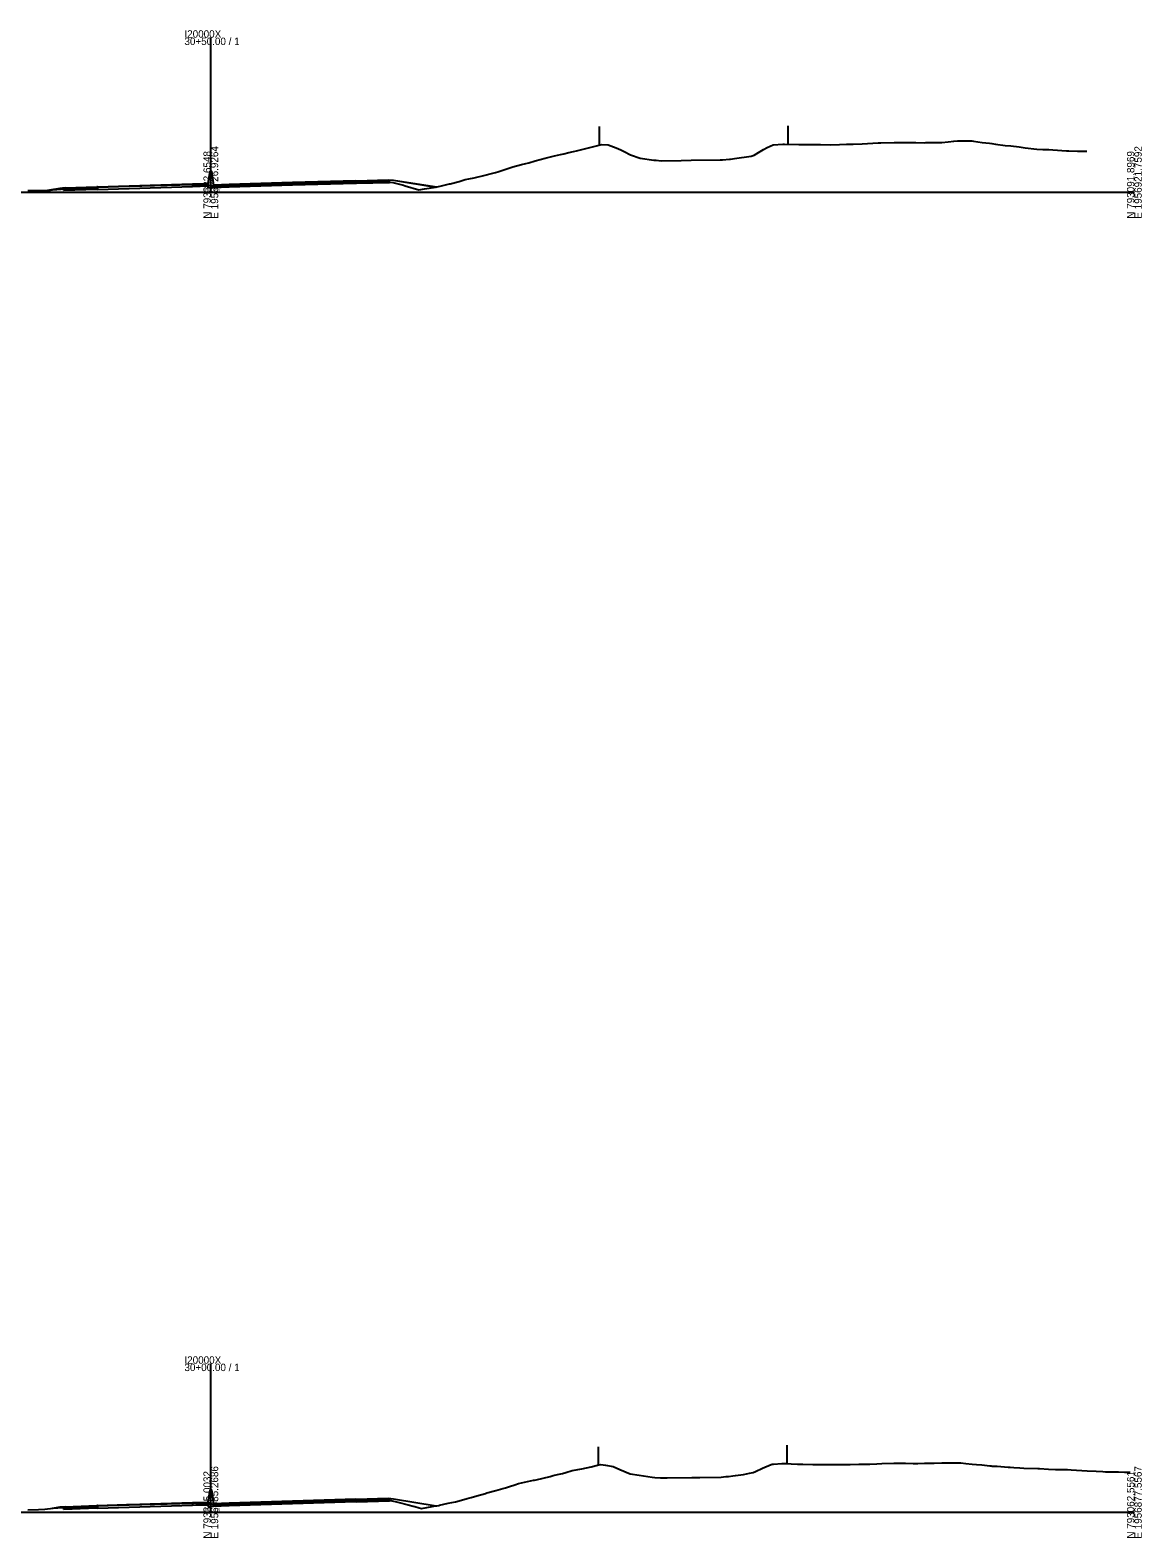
# Model space of a CAD drawing. Extents: x -4026 to 9638, y -10 to 19609.
# Drawn here: x -2718 to -2297, y -10 to 561 of the extents above; entities that cross this region are included whole.
import ezdxf

# ---------------------------------------------------------------- set-up
doc = ezdxf.new("R2010")
doc.units = 0
for name, color, linetype in [('RD_EX_Fence_Other', 7, 'Continuous'), ('RD_GPK_XS_Cell', 7, 'Continuous'), ('RD_XS_Base', 7, 'Continuous'), ('RD_XS_ExGround', 7, 'Continuous'), ('RD_XS_Greenside', 7, 'Continuous'), ('RD_XS_MedBWall', 7, 'Continuous'), ('RD_XS_Pave', 7, 'Continuous'), ('RD_XS_PaveOvlay', 7, 'Continuous'), ('RD_XS_TieSlope', 7, 'Continuous'), ('RD_XS_TX_Elev_EX', 7, 'Continuous')]:
    doc.layers.add(name, color=color, linetype=linetype)

msp = doc.modelspace()

# ---------------------------------------------------------------- linework, layer by layer
at = {"layer": 'RD_EX_Fence_Other'}
for p, q in [((-2502.77, 524.9), (-2502.77, 517.9)), ((-2431.34, 525.15), (-2431.34, 518.15)), ((-2503.21, 24.84), (-2503.21, 17.84)), ((-2431.68, 25.41), (-2431.68, 18.41))]:
    msp.add_line(p, q, dxfattribs=at)
at = {"layer": 'RD_GPK_XS_Cell'}
for p, q in [((-2650, 500), (-2650, 558.57)), ((-3000, 500), (-2650, 500)), ((-2650, 500), (-2300, 500)), ((-2650, 0), (-2650, 56.27)), ((-3000, 0), (-2650, 0)), ((-2650, 0), (-2300, 0))]:
    msp.add_line(p, q, dxfattribs=at)
at = {"layer": 'RD_XS_Base'}
for points in [[(-2657, 502.86), (-2681, 502.14), (-2693, 501.78)], [(-2651, 503.05), (-2657, 502.86)], [(-2657, 502.86), (-2657, 502.19)], [(-2651, 502.38), (-2651, 503.05)], [(-2649, 502.37), (-2643, 502.61)], [(-2643, 502.61), (-2619, 503.33), (-2595, 504.05)], [(-2595, 503.38), (-2619, 502.66), (-2643, 501.94)], [(-2643, 501.94), (-2643, 502.61)], [(-2595, 504.05), (-2594.75, 504.06)], [(-2595, 503.38), (-2595, 504.05)], [(-2594.75, 503.39), (-2595, 503.38)], [(-2582.25, 504.43), (-2582.75, 504.42), (-2594.75, 504.06)], [(-2594.75, 504.06), (-2594.75, 503.39)], [(-2594.75, 503.39), (-2582.25, 503.76)], [(-2582.25, 503.76), (-2582.25, 504.43)], [(-2705.75, 501.28), (-2705.25, 501.3), (-2693.25, 501.77)], [(-2705.75, 500.61), (-2705.75, 501.28)], [(-2693.25, 501.1), (-2705.75, 500.61)], [(-2693.25, 501.77), (-2693, 501.78)], [(-2693.25, 501.1), (-2693.25, 501.77)], [(-2693, 501.11), (-2693.25, 501.1)], [(-2693, 501.11), (-2681, 501.47), (-2657, 502.19)], [(-2693, 501.78), (-2693, 501.11)], [(-2657, 502.19), (-2651, 502.38)], [(-2649, 501.7), (-2649, 502.37)], [(-2643, 501.94), (-2649, 501.7)], [(-2705.75, 1.76), (-2705.25, 1.78), (-2693.25, 2.25)], [(-2705.75, 1.09), (-2705.75, 1.76)], [(-2693.25, 1.58), (-2705.75, 1.09)], [(-2693.25, 2.25), (-2693, 2.26)], [(-2693.25, 1.58), (-2693.25, 2.25)], [(-2693, 1.59), (-2693.25, 1.58)], [(-2657, 3.35), (-2681, 2.63), (-2693, 2.26)], [(-2693, 1.59), (-2681, 1.96), (-2657, 2.68)], [(-2693, 2.26), (-2693, 1.59)], [(-2651, 3.53), (-2657, 3.35)], [(-2657, 3.35), (-2657, 2.68)], [(-2657, 2.68), (-2651, 2.86)], [(-2651, 2.86), (-2651, 3.53)], [(-2649, 2.9), (-2643, 3.14)], [(-2649, 2.23), (-2649, 2.9)], [(-2643, 2.47), (-2649, 2.23)], [(-2643, 3.14), (-2619, 3.87), (-2595, 4.58)], [(-2595, 3.91), (-2619, 3.2), (-2643, 2.47)], [(-2643, 2.47), (-2643, 3.14)], [(-2595, 4.58), (-2594.75, 4.59)], [(-2595, 3.91), (-2595, 4.58)], [(-2594.75, 3.92), (-2595, 3.91)], [(-2582.25, 4.97), (-2582.75, 4.96), (-2594.75, 4.59)], [(-2594.75, 4.59), (-2594.75, 3.92)], [(-2594.75, 3.92), (-2582.25, 4.3)], [(-2582.25, 4.3), (-2582.25, 4.97)]]:
    msp.add_lwpolyline(points, dxfattribs=at)
at = {"layer": 'RD_XS_ExGround'}
for points in [[(-2719.34, 500.67), (-2717.96, 500.65), (-2717.22, 500.65), (-2714.42, 500.66), (-2711.93, 500.78), (-2710.81, 500.83), (-2710.06, 500.9), (-2703.43, 501.42), (-2702.25, 501.52), (-2693.3, 501.94), (-2681.86, 502.29), (-2674.2, 502.53), (-2670.1, 502.65), (-2662.32, 502.85), (-2658.4, 502.95), (-2655.83, 502.9), (-2652.91, 502.85), (-2651.82, 502.77), (-2650, 502.62), (-2649.02, 502.55), (-2644.92, 502.82), (-2643.82, 502.89), (-2643.25, 502.91), (-2641.06, 503), (-2640.26, 503.03), (-2639.84, 503.04), (-2637.84, 503.11), (-2632.31, 503.24), (-2631.6, 503.26), (-2620.57, 503.59), (-2619.97, 503.61), (-2618.47, 503.64), (-2609, 503.86), (-2600.66, 504.09), (-2600.02, 504.11), (-2599.06, 504.11), (-2590.13, 504.11), (-2588.31, 504.04), (-2586.89, 503.99), (-2586.24, 503.97), (-2583.67, 503.86), (-2581.07, 503.64), (-2577.47, 502.82), (-2576.95, 502.67), (-2576.39, 502.5), (-2571.21, 500.98), (-2568.98, 501.32), (-2568.19, 501.43), (-2565.61, 501.86), (-2563.05, 502.37), (-2559.59, 503.16), (-2559.24, 503.25), (-2555.85, 504.12), (-2553.57, 504.8), (-2552.24, 505.15), (-2550.26, 505.53), (-2548.64, 505.84), (-2547.56, 506.09), (-2542.07, 507.53), (-2541.27, 507.75), (-2535.52, 509.64), (-2532.29, 510.5), (-2530.62, 510.91), (-2529.5, 511.21), (-2527.02, 511.92), (-2523.31, 512.94), (-2519.81, 513.79), (-2517.46, 514.29), (-2516.2, 514.6), (-2514.33, 515.07), (-2512.6, 515.5), (-2511.44, 515.72), (-2505.35, 517.25), (-2501.79, 518.15), (-2499.4, 517.92), (-2496.36, 516.85), (-2494.58, 516.05), (-2493.39, 515.48), (-2490.98, 514.23), (-2487.32, 512.93), (-2482.11, 512.17), (-2481.17, 512.11), (-2479.31, 511.97), (-2471.69, 512.07), (-2467.99, 512.11), (-2456.93, 512.29), (-2456.14, 512.3), (-2453.39, 512.52), (-2453.05, 512.56), (-2451.59, 512.74), (-2445.24, 513.69), (-2444.13, 514.06), (-2442.47, 515.06), (-2440.52, 516.16), (-2439.22, 516.95), (-2436.92, 517.95), (-2433.2, 518.17), (-2432.61, 518.16), (-2427.18, 518.1), (-2424.51, 518.1), (-2421.16, 518.05), (-2418.9, 518.12), (-2415.14, 518.03), (-2411.69, 518.12), (-2409.12, 518.23), (-2408.09, 518.26), (-2406.54, 518.28), (-2403.1, 518.37), (-2397.09, 518.76), (-2396.12, 518.78), (-2391.07, 518.88), (-2388.58, 518.88), (-2386.47, 518.82), (-2385.05, 518.84), (-2382.86, 518.85), (-2379.6, 518.77), (-2379.03, 518.79), (-2377.88, 518.8), (-2373.01, 518.91), (-2370.62, 519.08), (-2368.45, 519.39), (-2366.99, 519.49), (-2364.84, 519.52), (-2361.63, 519.46), (-2360.97, 519.4), (-2357.63, 518.88), (-2354.95, 518.6), (-2354.03, 518.47), (-2352.65, 518.27), (-2348.94, 517.71), (-2346.82, 517.54), (-2343.67, 517.16), (-2342.92, 517.07), (-2341.39, 516.87), (-2336.9, 516.28), (-2334.69, 516.17), (-2332.41, 516.14), (-2330.88, 516.06), (-2325.71, 515.69), (-2325.2, 515.65), (-2324.86, 515.64), (-2321.6, 515.52), (-2318.84, 515.57), (-2317.99, 515.57)], [(-2719.32, 0.98), (-2715.25, 1), (-2712.89, 1.2), (-2709.74, 1.52), (-2708.03, 1.67), (-2705.8, 1.84), (-2705.27, 1.88), (-2704.08, 1.94), (-2701.83, 2.11), (-2698.98, 2.25), (-2693.26, 2.52), (-2685.55, 2.78), (-2681.95, 2.9), (-2679.16, 2.98), (-2670.34, 3.2), (-2665.13, 3.34), (-2658.54, 3.53), (-2655.65, 3.46), (-2653.08, 3.4), (-2651.06, 3.24), (-2650, 3.16), (-2649.38, 3.12), (-2646.43, 3.3), (-2644.16, 3.44), (-2641.67, 3.53), (-2638.91, 3.63), (-2637.89, 3.66), (-2635.82, 3.74), (-2634.57, 3.77), (-2634.03, 3.78), (-2632.43, 3.82), (-2631.79, 3.84), (-2627.99, 3.95), (-2620.27, 4.16), (-2611.8, 4.35), (-2609.08, 4.41), (-2599.9, 4.67), (-2599.55, 4.68), (-2589.7, 4.74), (-2585.57, 4.57), (-2583.58, 4.49), (-2582.91, 4.46), (-2581.67, 4.42), (-2581.24, 4.34), (-2579.16, 3.82), (-2575.26, 2.87), (-2573.3, 2.33), (-2572.69, 2.18), (-2571.05, 1.72), (-2570.13, 1.47), (-2566.11, 2.18), (-2564.82, 2.4), (-2564.39, 2.47), (-2563.62, 2.62), (-2563.29, 2.68), (-2560.01, 3.39), (-2557.3, 4), (-2555.02, 4.57), (-2552.79, 5.15), (-2551.32, 5.55), (-2549.18, 6.19), (-2545.92, 7.14), (-2545.34, 7.31), (-2541.96, 8.28), (-2539.35, 8.98), (-2538.35, 9.26), (-2536.82, 9.77), (-2534.74, 10.41), (-2533.37, 10.88), (-2531.13, 11.36), (-2527.72, 12.1), (-2527.38, 12.17), (-2526.74, 12.33), (-2521.4, 13.59), (-2520.3, 13.9), (-2518.62, 14.3), (-2516.69, 14.72), (-2515.42, 15.12), (-2513.08, 15.81), (-2509.43, 16.4), (-2505.86, 17.17), (-2503.45, 17.79), (-2502.24, 18.08), (-2500.41, 17.9), (-2497.46, 17.34), (-2495.02, 16.19), (-2491.12, 14.51), (-2487.65, 14), (-2482.68, 13.27), (-2481.72, 13.2), (-2479.61, 13.04), (-2477.1, 13.07), (-2467.75, 13.15), (-2464.65, 13.2), (-2456.6, 13.33), (-2454.79, 13.49), (-2453.78, 13.57), (-2452.16, 13.77), (-2451.11, 13.92), (-2448.09, 14.32), (-2445.81, 14.83), (-2444.48, 15.1), (-2443.61, 15.49), (-2440.87, 16.74), (-2437.62, 18.09), (-2437.26, 18.23), (-2436.71, 18.26), (-2433.65, 18.51), (-2431.64, 18.41), (-2430.04, 18.28), (-2427.61, 18.21), (-2425.66, 18.18), (-2421.91, 18.15), (-2419.67, 18.14), (-2418.51, 18.13), (-2415.6, 18.14), (-2413.69, 18.13), (-2411.99, 18.14), (-2409.41, 18.12), (-2408.38, 18.13), (-2407.7, 18.14), (-2404.44, 18.16), (-2401.72, 18.19), (-2401.16, 18.19), (-2400.3, 18.22), (-2397.55, 18.33), (-2395.74, 18.46), (-2391.2, 18.62), (-2390.33, 18.62), (-2389.75, 18.62), (-2386.72, 18.56), (-2383.77, 18.5), (-2382.1, 18.5), (-2379.5, 18.57), (-2377.78, 18.58), (-2375.89, 18.61), (-2373, 18.7), (-2371.8, 18.76), (-2369.49, 18.71), (-2365.82, 18.75), (-2363.9, 18.51), (-2361.45, 18.17), (-2359.83, 18.06), (-2357.84, 17.92), (-2354.8, 17.61), (-2354.23, 17.56), (-2353.85, 17.52), (-2352.02, 17.4), (-2347.86, 17.1), (-2347.01, 17.03), (-2345.7, 16.98), (-2343.4, 16.86), (-2341.88, 16.76), (-2336.6, 16.57), (-2335.9, 16.53), (-2332.56, 16.33), (-2329.91, 16.21), (-2328.95, 16.14), (-2327.5, 16.14), (-2325.34, 16.15), (-2323.93, 16.09), (-2317.94, 15.69), (-2314.51, 15.53), (-2311.96, 15.41), (-2310.9, 15.37), (-2309.3, 15.36), (-2305.98, 15.27), (-2303.68, 15.21), (-2302.43, 15.19), (-2301.61, 15.18)]]:
    msp.add_lwpolyline(points, dxfattribs=at)
at = {"layer": 'RD_XS_Greenside'}
for points in [[(-2582.75, 504.75), (-2580.75, 504.59)], [(-2580.75, 504.59), (-2564.75, 501.92)], [(-2580.75, 504.59), (-2564.38, 502.1)], [(-2707.25, 501.47), (-2711.19, 500.81)], [(-2705.25, 501.63), (-2707.25, 501.47)], [(-2707.25, 1.95), (-2710.09, 1.48)], [(-2705.25, 2.11), (-2707.25, 1.95)], [(-2582.75, 5.29), (-2580.75, 5.12)], [(-2580.75, 5.12), (-2564.62, 2.43)]]:
    msp.add_lwpolyline(points, dxfattribs=at)
at = {"layer": 'RD_XS_MedBWall'}
for points in [[(-2651, 503.38), (-2650.25, 508.05)], [(-2651, 501.7), (-2651, 503.05), (-2651, 503.38)], [(-2650.25, 508.05), (-2649.75, 508.05), (-2649, 502.7)], [(-2649, 502.7), (-2649, 502.37), (-2649, 501.7)], [(-2649, 501.7), (-2651, 501.7)], [(-2651, 3.86), (-2650.25, 8.53)], [(-2650.25, 8.53), (-2649.75, 8.53), (-2649, 3.23)], [(-2651, 2.23), (-2651, 3.53), (-2651, 3.86)], [(-2649, 2.23), (-2651, 2.23)], [(-2649, 3.23), (-2649, 2.9), (-2649, 2.23)]]:
    msp.add_lwpolyline(points, dxfattribs=at)
at = {"layer": 'RD_XS_Pave'}
for points in [[(-2693, 501.95), (-2681, 502.31), (-2657, 503.03)], [(-2657, 502.86), (-2681, 502.14), (-2693, 501.78)], [(-2657, 503.03), (-2651, 503.22)], [(-2651, 503.05), (-2657, 502.86)], [(-2657, 503.03), (-2657, 502.86)], [(-2651, 503.22), (-2651, 503.05)], [(-2643, 502.78), (-2649, 502.54)], [(-2649, 502.37), (-2643, 502.61)], [(-2595, 504.22), (-2619, 503.5), (-2643, 502.78)], [(-2643, 502.61), (-2619, 503.33), (-2595, 504.05)], [(-2643, 502.78), (-2643, 502.61)], [(-2595, 504.22), (-2594.75, 504.23)], [(-2595, 504.05), (-2595, 504.22)], [(-2594.75, 504.06), (-2595, 504.05)], [(-2582.75, 504.59), (-2594.75, 504.23)], [(-2594.75, 504.06), (-2582.75, 504.42)], [(-2594.75, 504.23), (-2594.75, 504.06)], [(-2582.75, 504.42), (-2582.75, 504.59)], [(-2705.25, 501.46), (-2693.25, 501.94)], [(-2693.25, 501.77), (-2705.25, 501.3)], [(-2705.25, 501.3), (-2705.25, 501.46)], [(-2693.25, 501.94), (-2693, 501.95)], [(-2693.25, 501.77), (-2693.25, 501.94)], [(-2693, 501.78), (-2693.25, 501.77)], [(-2693, 501.95), (-2693, 501.78)], [(-2649, 502.54), (-2649, 502.37)], [(-2705.25, 1.95), (-2693.25, 2.42)], [(-2693.25, 2.25), (-2705.25, 1.78)], [(-2705.25, 1.78), (-2705.25, 1.95)], [(-2693.25, 2.42), (-2693, 2.43)], [(-2693.25, 2.25), (-2693.25, 2.42)], [(-2693, 2.26), (-2693.25, 2.25)], [(-2693, 2.43), (-2681, 2.8), (-2657, 3.52)], [(-2657, 3.35), (-2681, 2.63), (-2693, 2.26)], [(-2693, 2.43), (-2693, 2.26)], [(-2657, 3.52), (-2651, 3.7)], [(-2651, 3.53), (-2657, 3.35)], [(-2657, 3.52), (-2657, 3.35)], [(-2651, 3.7), (-2651, 3.53)], [(-2643, 3.31), (-2649, 3.07)], [(-2649, 2.9), (-2643, 3.14)], [(-2649, 3.07), (-2649, 2.9)], [(-2595, 4.75), (-2619, 4.03), (-2643, 3.31)], [(-2643, 3.14), (-2619, 3.87), (-2595, 4.58)], [(-2643, 3.31), (-2643, 3.14)], [(-2595, 4.75), (-2594.75, 4.76)], [(-2595, 4.58), (-2595, 4.75)], [(-2594.75, 4.59), (-2595, 4.58)], [(-2582.75, 5.12), (-2594.75, 4.76)], [(-2594.75, 4.59), (-2582.75, 4.96)], [(-2594.75, 4.76), (-2594.75, 4.59)], [(-2582.75, 4.96), (-2582.75, 5.12)]]:
    msp.add_lwpolyline(points, dxfattribs=at)
at = {"layer": 'RD_XS_PaveOvlay'}
for points in [[(-2693, 502.12), (-2681, 502.48), (-2657, 503.2)], [(-2657, 503.03), (-2681, 502.31), (-2693, 501.95)], [(-2657, 503.2), (-2651, 503.38)], [(-2651, 503.22), (-2657, 503.03)], [(-2657, 503.2), (-2657, 503.03)], [(-2651, 503.38), (-2651, 503.22)], [(-2643, 502.95), (-2649, 502.7)], [(-2649, 502.54), (-2643, 502.78)], [(-2649, 502.7), (-2649, 502.54)], [(-2595, 504.39), (-2619, 503.67), (-2643, 502.95)], [(-2643, 502.78), (-2619, 503.5), (-2595, 504.22)], [(-2643, 502.95), (-2643, 502.78)], [(-2595, 504.22), (-2595, 504.39)], [(-2595, 504.39), (-2594.75, 504.39)], [(-2594.75, 504.23), (-2595, 504.22)], [(-2594.75, 504.39), (-2582.75, 504.75)], [(-2582.75, 504.59), (-2594.75, 504.23)], [(-2594.75, 504.39), (-2594.75, 504.23)], [(-2582.75, 504.75), (-2582.75, 504.59)], [(-2705.25, 501.63), (-2693.25, 502.11)], [(-2693.25, 501.94), (-2705.25, 501.46)], [(-2705.25, 501.46), (-2705.25, 501.63)], [(-2693, 502.12), (-2693.25, 502.11)], [(-2693.25, 502.11), (-2693.25, 501.94)], [(-2693.25, 501.94), (-2693, 501.95)], [(-2693, 501.95), (-2693, 502.12)], [(-2705.25, 2.11), (-2693.25, 2.59)], [(-2693.25, 2.42), (-2705.25, 1.95)], [(-2705.25, 1.95), (-2705.25, 2.11)], [(-2693, 2.6), (-2693.25, 2.59)], [(-2693.25, 2.59), (-2693.25, 2.42)], [(-2693.25, 2.42), (-2693, 2.43)], [(-2693, 2.6), (-2681, 2.96), (-2657, 3.68)], [(-2657, 3.52), (-2681, 2.8), (-2693, 2.43)], [(-2693, 2.43), (-2693, 2.6)], [(-2657, 3.68), (-2651, 3.86)], [(-2651, 3.7), (-2657, 3.52)], [(-2657, 3.68), (-2657, 3.52)], [(-2651, 3.86), (-2651, 3.7)], [(-2643, 3.48), (-2649, 3.23)], [(-2649, 3.07), (-2643, 3.31)], [(-2649, 3.23), (-2649, 3.07)], [(-2595, 4.92), (-2619, 4.2), (-2643, 3.48)], [(-2643, 3.31), (-2619, 4.03), (-2595, 4.75)], [(-2643, 3.48), (-2643, 3.31)], [(-2595, 4.92), (-2594.75, 4.93)], [(-2595, 4.75), (-2595, 4.92)], [(-2594.75, 4.76), (-2595, 4.75)], [(-2594.75, 4.93), (-2582.75, 5.29)], [(-2582.75, 5.12), (-2594.75, 4.76)], [(-2594.75, 4.93), (-2594.75, 4.76)], [(-2582.75, 5.29), (-2582.75, 5.12)]]:
    msp.add_lwpolyline(points, dxfattribs=at)
at = {"layer": 'RD_XS_TieSlope'}
msp.add_lwpolyline([(-2564.75, 501.92), (-2564.38, 502.1)], dxfattribs=at)

# ---------------------------------------------------------------- texts
at = {"layer": 'RD_GPK_XS_Cell'}
for s, p in [('I20000X', (-2660, 558.57)), ('30+50.00 / 1', (-2660, 555.77)), ('I20000X', (-2660, 56.27)), ('30+00.00 / 1', (-2660, 53.47))]:
    msp.add_text(s, height=2.8, dxfattribs=at).set_placement(p)
for s, p in [('N 793382.6548', (-2650, 490)), ('E 1956726.9264', (-2647.2, 490)), ('N 793091.8969', (-2300, 490)), ('E 1956921.7592', (-2297.2, 490)), ('E 1956685.2686', (-2647.2, -10)), ('E 1956877.5567', (-2297.2, -10)), ('N 793355.0032', (-2650, -10)), ('N 793062.5561', (-2300, -10))]:
    msp.add_text(s, height=2.8, rotation=90, dxfattribs=at).set_placement(p)
at = {"layer": 'RD_XS_TX_Elev_EX'}
for s, p in [('345.62', (-2652.8, 499.62)), ('347.16', (-2652.82, 0.16))]:
    msp.add_text(s, height=1.5, dxfattribs=at).set_placement(p)

doc.saveas('drawing.dxf')
